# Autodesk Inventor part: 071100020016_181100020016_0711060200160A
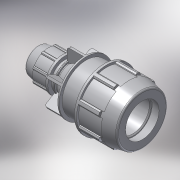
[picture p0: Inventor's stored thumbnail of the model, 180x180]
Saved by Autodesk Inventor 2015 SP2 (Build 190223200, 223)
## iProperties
Created: 2017-02
Part Number: 071100020016_181100020016_0711060200160A
Material: PVC-Piping
Description: PLASSON REDUCING COUPLER 20-16
Document SubType Name: Modeling
Designer: KIM
Mass: 92.6774 g
Surface Area: 199.44 cm^2
Volume: 66.1981 cm^3
Density: 1.4 g/cm^3
Appearance: Smooth - White
Author: KIM
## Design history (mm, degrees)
derived "07110.ipt"
feature "Solid1::07110.ipt"
tag "TaggingFeature1"
body "Solid1"
other parameters: "d4" = 9.25, "d5" = 15.85714, "d7" = 48, "d9" = 15.85714, "d11" = 1.58571, "d12" = 38.4, "d13" = 120 deg, "d15" = 12 deg, "d16" = 43.2, "d18" = 1, "d19" = 35 deg, "d20" = 17.5 deg, "d21" = 44.64, "d23" = 0, "d25" = 360 deg, "d27" = 0.96, "d42" = 24.42, "d46" = 0.6, "d51" = 111, "d52" = 15.85714, "d53" = 12 deg, "d54" = 57, "d56" = 24, "d57" = 16, "d58" = 18, "d59" = 14.4, "d60" = 35.1, "d61" = 31.2, "d62" = 11.1, "d63" = 17.76, "d64" = 120 deg, "d65" = 39, "d68" = 7.92857, "d74" = 36.27, "d75" = 35 deg, "d76" = 17.5 deg, "d78" = 0, "d80" = 360 deg, "d85" = 0.78, "d88" = 0.32, "d94" = 33.6, "d97" = 2.33333, "d98" = 2.6, "d99" = 0, "d100" = 1.92, "d102" = 360 deg, "d104" = 2, "d106" = 0, "d107" = 2.6, "d108" = 0, "d109" = 2.6, "d110" = 0, "E_" = 48, "H_" = 111, "l_" = 57, "d_1" = 16, "E_1" = 39, "d96" = 7
